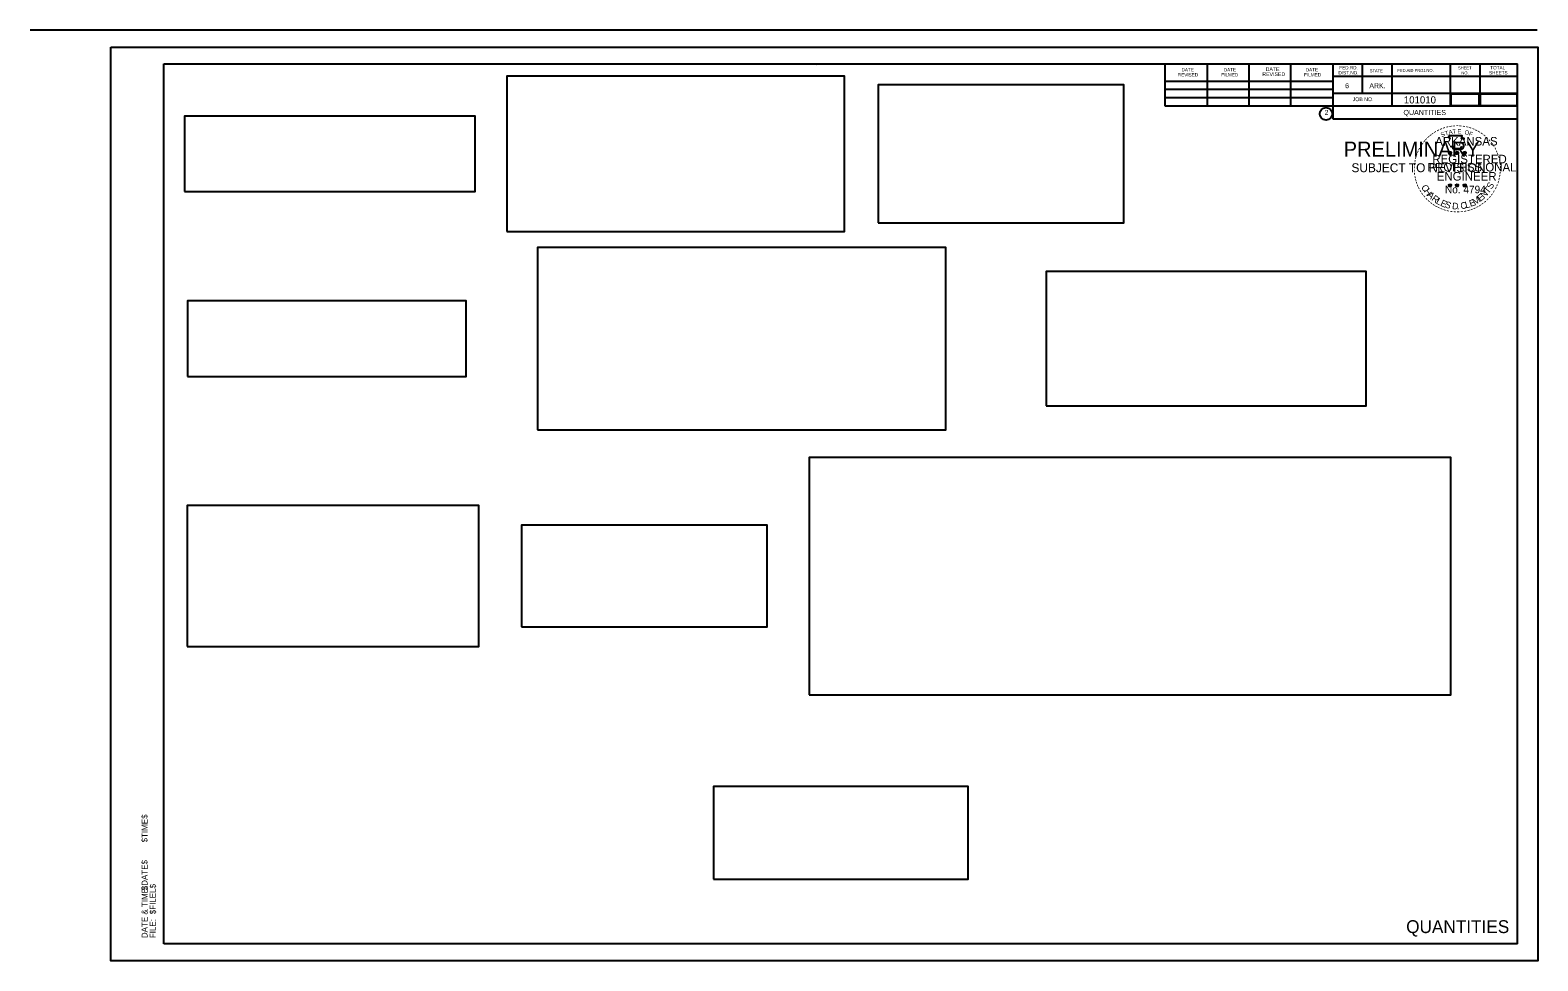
# Model space of a CAD drawing. Extents: x 9844 to 18514, y 8651 to 12569.
# Drawn here: x 11618 to 13378, y 9980 to 11067 of the extents above; entities that cross this region are included whole.
import ezdxf

# ---------------------------------------------------------------- set-up
doc = ezdxf.new("R2010")
doc.units = 0
for name, color, linetype in [('_Drafting 1', 7, 'Continuous'), ('Default', 7, 'Continuous'), ('Quantities', 7, 'Continuous'), ('R_Border Notes', 7, 'Continuous'), ('R_No Plot', 7, 'Continuous'), ('STAMP_PE_CRAFTON-SIGNATURE', 7, 'Continuous'), ('STAMP_PE_SEAL-INFO', 7, 'Continuous'), ('STAMP_PE_TXT', 7, 'Continuous'), ('STAMP_PRELIMINARY', 7, 'Continuous'), ('Total_Pages', 7, 'Continuous')]:
    doc.layers.add(name, color=color, linetype=linetype)

msp = doc.modelspace()

# ---------------------------------------------------------------- linework, layer by layer
at = {"layer": '_Drafting 1'}
for points in [[(11801, 10347), (12141.6, 10347), (12141.6, 10511.6), (11801, 10511.6)], [(12191.5, 10369.9), (12478.5, 10369.9), (12478.5, 10488.7), (12191.5, 10488.7)]]:
    msp.add_lwpolyline(points, close=True, dxfattribs=at)
at = {"layer": 'Quantities'}
for points in [[(12174.5, 10831.6), (12568.8, 10831.6), (12568.8, 11012.9), (12174.5, 11012.9)], [(12608.1, 10841.8), (12895.1, 10841.8), (12895.1, 11002.7), (12608.1, 11002.7)], [(11798.1, 10878.2), (12137.6, 10878.2), (12137.6, 10966.3), (11798.1, 10966.3)], [(12210.4, 10600), (12686.9, 10600), (12686.9, 10813.1), (12210.4, 10813.1)], [(12804.3, 10628), (13178.1, 10628), (13178.1, 10785.1), (12804.3, 10785.1)], [(11801.4, 10662.5), (12126.9, 10662.5), (12126.9, 10750.6), (11801.4, 10750.6)], [(12527.3, 10290.8), (13276.8, 10290.8), (13276.8, 10567.9), (12527.3, 10567.9)], [(12415.6, 10075.4), (12713, 10075.4), (12713, 10183.7), (12415.6, 10183.7)]]:
    msp.add_lwpolyline(points, close=True, dxfattribs=at)
at = {"layer": 'R_No Plot'}
msp.add_lwpolyline([(13276.7, 10978.6), (13310, 10978.6), (13310, 10991.9), (13276.7, 10991.9)], close=True, dxfattribs=at)
at = {"layer": 'STAMP_PE_SEAL-INFO'}
msp.add_lwpolyline([(11711.8, 11046.8), (13378.5, 11046.8), (13378.5, 9980.1), (11711.8, 9980.1)], close=True, dxfattribs=at)
at = {"layer": 'STAMP_PE_TXT'}
for p, q in [((13274.1, 10924), (13275.9, 10923.5)), ((13274.1, 10924), (13275.4, 10923.8)), ((13274.1, 10924), (13275.3, 10923.4)), ((13274.8, 10922), (13275.9, 10923.5)), ((13274.8, 10922), (13275.4, 10923.2)), ((13274.8, 10922), (13275.8, 10923.1)), ((13275.9, 10925.3), (13275.7, 10924.1)), ((13276.9, 10922), (13275.8, 10923.1)), ((13275.9, 10923.5), (13275.9, 10925.3)), ((13275.9, 10925.3), (13276.1, 10924.1)), ((13277.6, 10924), (13275.9, 10923.5)), ((13276.9, 10922), (13275.9, 10923.5)), ((13277.6, 10924), (13276.2, 10923.8)), ((13276.9, 10922), (13276.2, 10923.5)), ((13277.6, 10924), (13276.6, 10923.5)), ((13282.5, 10924), (13284.2, 10923.5)), ((13282.5, 10924), (13283.7, 10923.8)), ((13282.5, 10924), (13283.6, 10923.4)), ((13283.1, 10922), (13284.2, 10923.5)), ((13283.1, 10922), (13283.8, 10923.2)), ((13283.1, 10922), (13284.2, 10923.1)), ((13284.2, 10925.3), (13284, 10924.1)), ((13284.2, 10923.5), (13284.2, 10925.3)), ((13284.2, 10925.3), (13284.5, 10924.1)), ((13285.9, 10924), (13284.2, 10923.5)), ((13285.3, 10922), (13284.2, 10923.5)), ((13285.3, 10922), (13284.2, 10923.1)), ((13285.9, 10924), (13284.5, 10923.8)), ((13285.3, 10922), (13284.6, 10923.5)), ((13285.9, 10924), (13284.9, 10923.5)), ((13291.3, 10924), (13293, 10923.4)), ((13291.3, 10924), (13292.5, 10923.8)), ((13291.3, 10924), (13292.5, 10923.4)), ((13291.9, 10921.9), (13293, 10923.4)), ((13291.9, 10921.9), (13292.6, 10923.2)), ((13291.9, 10921.9), (13293, 10923)), ((13293, 10925.3), (13292.8, 10924)), ((13293, 10923.4), (13293, 10925.3)), ((13293, 10925.3), (13293.3, 10924)), ((13294.8, 10924), (13293, 10923.4)), ((13294.1, 10921.9), (13293, 10923.4)), ((13294.1, 10921.9), (13293, 10923)), ((13294.8, 10924), (13293.3, 10923.7)), ((13294.1, 10921.9), (13293.4, 10923.4)), ((13294.8, 10924), (13293.7, 10923.5)), ((13274.1, 10886.2), (13275.8, 10885.6)), ((13274.1, 10886.2), (13275.4, 10886)), ((13274.1, 10886.2), (13275.3, 10885.6)), ((13274.8, 10884.1), (13275.8, 10885.6)), ((13274.8, 10884.1), (13275.4, 10885.4)), ((13274.8, 10884.1), (13275.8, 10885.2)), ((13275.8, 10887.4), (13275.6, 10886.2)), ((13275.8, 10885.6), (13275.8, 10887.4)), ((13275.8, 10887.4), (13276.1, 10886.2)), ((13277.6, 10886.2), (13275.8, 10885.6)), ((13276.9, 10884.1), (13275.8, 10885.6)), ((13276.9, 10884.1), (13275.8, 10885.2)), ((13277.6, 10886.2), (13276.1, 10885.9)), ((13276.9, 10884.1), (13276.2, 10885.6)), ((13277.6, 10886.2), (13276.6, 10885.7)), ((13282.4, 10886.2), (13284.2, 10885.6)), ((13282.4, 10886.2), (13283.7, 10886)), ((13282.4, 10886.2), (13283.6, 10885.6)), ((13283.1, 10884.1), (13284.2, 10885.6)), ((13283.1, 10884.1), (13283.7, 10885.4)), ((13283.1, 10884.1), (13284.2, 10885.2)), ((13284.2, 10887.4), (13284, 10886.2)), ((13284.2, 10885.6), (13284.2, 10887.4)), ((13284.2, 10887.4), (13284.4, 10886.2)), ((13285.9, 10886.2), (13284.2, 10885.6)), ((13285.2, 10884.1), (13284.2, 10885.6)), ((13285.2, 10884.1), (13284.2, 10885.2)), ((13285.9, 10886.2), (13284.5, 10885.9)), ((13285.2, 10884.1), (13284.6, 10885.6)), ((13285.9, 10886.2), (13284.9, 10885.7)), ((13291.3, 10886.1), (13293, 10885.6)), ((13291.3, 10886.1), (13292.5, 10885.9)), ((13291.3, 10886.1), (13292.5, 10885.5)), ((13291.9, 10884.1), (13293, 10885.6)), ((13291.9, 10884.1), (13292.6, 10885.3)), ((13291.9, 10884.1), (13293, 10885.2)), ((13293, 10887.4), (13292.8, 10886.1)), ((13293, 10885.6), (13293, 10887.4)), ((13293, 10887.4), (13293.3, 10886.1)), ((13294.8, 10886.1), (13293, 10885.6)), ((13294.1, 10884.1), (13293, 10885.6)), ((13294.1, 10884.1), (13293, 10885.2)), ((13294.8, 10886.1), (13293.3, 10885.9)), ((13294.1, 10884.1), (13293.4, 10885.5)), ((13294.8, 10886.1), (13293.7, 10885.6))]:
    msp.add_line(p, q, dxfattribs=at)
for points in [[(13274.3, 10943.4), (13275.7, 10939.3)], [(13291.9, 10938.8), (13292.6, 10940.2), (13289.2, 10940.1), (13289.9, 10943.4), (13274.3, 10943.4)], [(13275.9, 10925.3), (13276.9, 10922), (13274.1, 10924), (13277.6, 10924), (13274.8, 10922), (13275.9, 10925.3)], [(13276.8, 10931.3), (13276.8, 10930.9), (13279.6, 10930.8), (13279.3, 10928.4), (13288.7, 10928.4), (13289.7, 10931.1)], [(13284.2, 10925.3), (13285.3, 10922), (13282.5, 10924), (13285.9, 10924), (13283.1, 10922), (13284.2, 10925.3)], [(13293, 10925.3), (13294.1, 10921.9), (13291.3, 10924), (13294.8, 10924), (13291.9, 10921.9), (13293, 10925.3)], [(13275.8, 10887.4), (13276.9, 10884.1), (13274.1, 10886.2), (13277.6, 10886.2), (13274.8, 10884.1), (13275.8, 10887.4)], [(13284.2, 10887.4), (13285.2, 10884.1), (13282.4, 10886.2), (13285.9, 10886.2), (13283.1, 10884.1), (13284.2, 10887.4)], [(13293, 10887.4), (13294.1, 10884.1), (13291.3, 10886.1), (13294.8, 10886.1), (13291.9, 10884.1), (13293, 10887.4)]]:
    msp.add_lwpolyline(points, dxfattribs=at)
for centre, radius in [((13275.9, 10923.5), 0.861), ((13275.9, 10923.5), 0.723), ((13275.9, 10923.5), 0.579), ((13275.9, 10923.5), 0.495), ((13275.9, 10923.5), 0.374), ((13275.9, 10923.5), 0.248), ((13275.9, 10923.5), 0.148), ((13284.2, 10923.5), 0.861), ((13284.2, 10923.5), 0.723), ((13284.2, 10923.5), 0.579), ((13284.2, 10923.5), 0.495), ((13284.2, 10923.5), 0.374), ((13284.2, 10923.5), 0.248), ((13284.2, 10923.5), 0.148), ((13293, 10923.4), 0.861), ((13293, 10923.4), 0.723), ((13293, 10923.4), 0.579), ((13293, 10923.4), 0.495), ((13293, 10923.4), 0.374), ((13293, 10923.4), 0.248), ((13293, 10923.4), 0.148), ((13275.8, 10885.6), 0.861), ((13275.8, 10885.6), 0.723), ((13275.8, 10885.6), 0.579), ((13275.8, 10885.6), 0.495), ((13275.8, 10885.6), 0.374), ((13275.8, 10885.6), 0.248), ((13275.8, 10885.6), 0.148), ((13284.2, 10885.6), 0.861), ((13284.2, 10885.6), 0.723), ((13284.2, 10885.6), 0.579), ((13284.2, 10885.6), 0.495), ((13284.2, 10885.6), 0.374), ((13284.2, 10885.6), 0.248), ((13284.2, 10885.6), 0.148), ((13293, 10885.6), 0.861), ((13293, 10885.6), 0.723), ((13293, 10885.6), 0.579), ((13293, 10885.6), 0.495), ((13293, 10885.6), 0.374), ((13293, 10885.6), 0.248), ((13293, 10885.6), 0.148)]:
    msp.add_circle(centre, radius, dxfattribs=at)
at = {"layer": 'STAMP_PRELIMINARY'}
for p, q in [((13377.7, 11066.7), (11617.7, 11066.7)), ((11773.8, 11027.3), (13354.7, 11027.3)), ((11773.8, 10000), (11773.8, 11027.3)), ((12536.4, 11026), (12536.4, 11026)), ((12536.4, 11026), (12536.4, 11026)), ((12943.4, 10977.9), (12943.4, 11027.3)), ((12992.7, 10977.9), (12992.7, 11026.3)), ((13041.5, 10977.9), (13041.5, 11026.3)), ((13089.9, 10977.9), (13089.9, 11026.3)), ((13139.2, 11027.3), (13139.2, 10963.3)), ((13173.4, 11027.3), (13173.4, 10992.6)), ((13208.1, 11027.3), (13208.1, 10977.9)), ((13276, 11027.3), (13276, 10977.9)), ((13310.7, 11027.3), (13310.7, 10977.9)), ((13354.7, 10000), (13354.7, 11027.3)), ((12943.4, 11007.2), (13139.2, 11007.2)), ((13354.7, 11012.6), (13139.2, 11012.6)), ((13354.7, 11012.7), (13354.7, 11012.7)), ((12943.4, 10997.9), (13139.2, 10997.9)), ((12943.4, 10988.2), (13139.2, 10988.2)), ((13354.7, 10992.6), (13139.2, 10992.6)), ((13354.7, 10977.9), (12943.4, 10977.9)), ((13139.2, 10963.3), (13354.7, 10963.3)), ((13354.7, 10000), (11773.8, 10000))]:
    msp.add_line(p, q, dxfattribs=at)
msp.add_circle((13131.1, 10969), 7.33, dxfattribs=at)
at = {"layer": 'Total_Pages'}
msp.add_lwpolyline([(13311.2, 10978.6), (13354.2, 10978.6), (13354.2, 10991.9), (13311.2, 10991.9)], close=True, dxfattribs=at)

# ---------------------------------------------------------------- texts
at = {"layer": 'Default'}
for s, height, p in [('$TIME$', 6.98, (11754.8, 10118.4)), ('$DATE$', 6.98, (11754.8, 10062.5)), ('DATE & TIME:', 6.984, (11754.8, 10006.6)), ('$FILEL$', 6.98, (11764.4, 10034.5)), ('FILE: ', 6.98, (11764.4, 10006.6))]:
    msp.add_text(s, height=height, rotation=90, dxfattribs=at).set_placement(p)
at = {"layer": 'R_Border Notes'}
for s, height, p in [('101010', 8.4, (13222, 10981.1)), ('QUANTITIES', 6, (13221.5, 10967.6))]:
    msp.add_text(s, height=height, dxfattribs=at).set_placement(p)
at = {"layer": 'STAMP_PE_CRAFTON-SIGNATURE'}
for s, height, p in [('PRELIMINARY', 17.5, (13151.7, 10919)), ('SUBJECT TO REVISION', 10.376, (13160.8, 10900.9))]:
    msp.add_text(s, height=height, dxfattribs=at).set_placement(p)
at = {"layer": 'STAMP_PE_TXT'}
for s, height, rotation, p in [('-', 8, 24.3072, (13264.9, 10947.7)), ('-', 8, 19.1761, (13268.1, 10949.1)), ('-', 8, 13.6302, (13271.8, 10950.3)), ('-', 8, 10.2193, (13275.2, 10951.1)), ('-', 8, 5.8968, (13278.8, 10951.6)), ('-', 8, 0.1862, (13282.7, 10952)), ('-', 8, 357.743, (13286.3, 10951.9)), ('-', 8, 352.1617, (13290, 10951.6)), ('-', 8, 347.2049, (13293.6, 10951.1)), ('-', 8, 342.3362, (13296.8, 10950.3)), ('-', 8, 337.8551, (13300.5, 10949.2)), ('-', 8, 54.2325, (13245, 10930.7)), ('-', 8, 50.6142, (13247, 10933.5)), ('-', 8, 48.4231, (13249.1, 10935.9)), ('-', 8, 42.9622, (13251.3, 10938.3)), ('-', 8, 38.9507, (13253.5, 10940.4)), ('-', 8, 36.2317, (13255.8, 10942.3)), ('-', 8, 34.0636, (13258.7, 10944.3)), ('-', 8, 28.7918, (13261.7, 10946.1)), ('S', 5, 21.594, (13266.1, 10941.8)), ('T', 5, 16.4036, (13270.7, 10943.5)), ('A', 5, 11.2132, (13274.8, 10944.7)), ('T', 5, 6.0228, (13279, 10945.6)), ('E', 5, 0.8323, (13284.6, 10946.1)), ('O', 5, 350.4515, (13292.6, 10945.1)), ('F', 5, 340.0707, (13297.4, 10943.9)), ('-', 8, 334.1211, (13303.6, 10947.8)), ('-', 8, 329.6409, (13306.5, 10946.4)), ('-', 8, 325.8627, (13309.7, 10944.6)), ('-', 8, 320.5297, (13312.8, 10942.5)), ('-', 8, 315.5786, (13315.8, 10940)), ('-', 8, 309.8797, (13318.6, 10937.3)), ('-', 8, 306.6522, (13321.3, 10934.3)), ('-', 8, 75.461, (13238.4, 10915.2)), ('-', 8, 72.3945, (13239.4, 10918.8)), ('-', 8, 67.7743, (13240.5, 10921.9)), ('-', 8, 62.8713, (13241.8, 10925)), ('-', 8, 58.0706, (13243.4, 10928)), ('-', 7, 303.6753, (13323.7, 10931.4)), ('-', 8, 299.6684, (13325.3, 10928.4)), ('-', 8, 294.6628, (13326.9, 10925.3)), ('-', 8, 290.5728, (13328.2, 10922.5)), ('-', 8, 285.1233, (13329.4, 10919.6)), ('-', 8, 89.0622, (13237.3, 10904.7)), ('-', 8, 94.1959, (13237.4, 10901.1)), ('-', 8, 98.9479, (13237.8, 10897.7)), ('-', 8, 85.1863, (13237.4, 10908.2)), ('-', 8, 81.2013, (13237.8, 10911.6)), ('-', 8, 280.5493, (13330.4, 10915.9)), ('-', 8, 276.5962, (13331.2, 10912)), ('-', 8, 263.5172, (13331.5, 10901.9)), ('-', 8, 274.3301, (13331.5, 10908.4)), ('-', 8, 269.9407, (13331.6, 10905.2)), ('-', 8, 101.7149, (13238.5, 10894.1)), ('-', 8, 105.4578, (13239.3, 10891.1)), ('-', 8, 109.0874, (13240.3, 10887.9)), ('-', 8, 114.0643, (13241.6, 10884.9)), ('-', 8, 115.7289, (13243.1, 10881.9)), ('C', 7.7, 296.9133, (13242, 10883.9)), ('H', 7.7, 303.2799, (13244.9, 10878.7)), ('T', 7.7, 51.5114, (13320.7, 10875.1)), ('S', 7.7, 57.878, (13324.3, 10880.3)), ('-', 8, 244.6197, (13327.3, 10885.1)), ('-', 8, 247.8887, (13328.6, 10888.3)), ('-', 8, 255.7626, (13329.7, 10891.8)), ('-', 8, 255.7626, (13330.6, 10895.3)), ('-', 8, 260.9953, (13331.2, 10898.6)), ('-', 8, 120.4471, (13244.9, 10878.9)), ('-', 8, 125.8934, (13246.9, 10876.1)), ('-', 8, 130.7181, (13249.3, 10873.4)), ('-', 8, 134.2238, (13251.8, 10870.6)), ('A', 7.7, 316.013, (13248.6, 10873.6)), ('-', 8, 138.9338, (13254.5, 10868.3)), ('-', 8, 144.6463, (13257.2, 10866.3)), ('R', 7.7, 322.3796, (13253.7, 10868.7)), ('L', 7.7, 328.7461, (13258.8, 10864.9)), ('E', 7.7, 335.1127, (13263.9, 10862.1)), ('S', 7.7, 341.4792, (13269.2, 10860)), ('D', 7.7, 354.2124, (13278, 10857.9)), ('C', 7.7, 6.9455, (13288.5, 10857.7)), ('L', 7.7, 13.3121, (13294.4, 10858.7)), ('E', 7.7, 19.6786, (13299.9, 10860.3)), ('M', 7.7, 32.4117, (13305, 10862.1)), ('E', 7.7, 38.7783, (13311.4, 10866.2)), ('N', 7.7, 45.1449, (13315.9, 10869.9)), ('-', 8, 215.7363, (13313.4, 10867.6)), ('-', 8, 221.0851, (13316.2, 10869.9)), ('-', 8, 225.7653, (13318.8, 10872.5)), ('-', 8, 231.2538, (13321.2, 10875.3)), ('-', 8, 233.8452, (13323.3, 10878.1)), ('-', 8, 239.0712, (13325.3, 10881.4)), ('-', 8, 148.0898, (13260, 10864.4)), ('-', 8, 151.5704, (13262.9, 10862.8)), ('-', 8, 154.6002, (13265.6, 10861.6)), ('-', 8, 158.5612, (13268.7, 10860.3)), ('-', 8, 162.7983, (13272.1, 10859.2)), ('-', 8, 167.5555, (13275.7, 10858.4)), ('-', 8, 173.1155, (13279.5, 10857.9)), ('-', 8, 176.5183, (13283.3, 10857.6)), ('-', 8, 181.5918, (13287, 10857.7)), ('.', 7.7, 0.5789, (13283.9, 10857.5)), ('-', 8, 185.8167, (13291, 10858.1)), ('-', 8, 191.2858, (13294.7, 10858.7)), ('-', 8, 195.4743, (13298.4, 10859.7)), ('-', 8, 200.7184, (13301.8, 10860.9)), ('-', 8, 204.2516, (13304.9, 10862.3)), ('-', 8, 207.3568, (13308, 10863.9)), ('-', 8, 212.2491, (13310.8, 10865.6))]:
    msp.add_text(s, height=height, rotation=rotation, dxfattribs=at).set_placement(p)
for s, height, p in [('ARKANSAS', 10, (13258.6, 10932)), ('REGISTERED', 10, (13255.2, 10911.2)), ('PROFESSIONAL', 10, (13249.5, 10901.7)), ('ENGINEER', 10, (13260.4, 10891.1)), ('No. 4794', 8.78, (13270, 10876.3))]:
    msp.add_text(s, height=height, dxfattribs=at).set_placement(p)
at = {"layer": 'STAMP_PRELIMINARY'}
for s, height, p in [('DATE', 3.91, (12962.4, 11018.5)), ('DATE', 3.91, (13011.7, 11018.5)), ('DATE', 4.4, (13060.6, 11019)), ('DATE', 3.91, (13107.5, 11018.5)), ('FED.RD.', 3.91, (13146.6, 11020.9)), ('SHEET', 3.42, (13285.3, 11020.9)), ('TOTAL', 3.91, (13322.9, 11020.9)), ('REVISED', 3.91, (12958, 11012.6)), ('FILMED', 3.91, (13008.8, 11012.6)), ('REVISED', 4.4, (13056.7, 11013.1)), ('FILMED', 3.91, (13105.5, 11012.6)), ('DIST.NO.', 3.91, (13145.6, 11015)), ('6', 5.86, (13153.4, 10998.9)), ('STATE', 3.42, (13182.2, 11017.5)), ('FED.AID PROJ.NO.', 3.42, (13214.5, 11018)), ('NO.', 3.42, (13289.2, 11015)), ('SHEETS', 3.91, (13321.5, 11015)), ('JOB NO.', 4.4, (13162.2, 10983.8)), ('ARK.', 5.86, (13181.7, 10998.9)), ('2', 5.86, (13129.5, 10967.7)), ('QUANTITIES', 15, (13224.7, 10012.5))]:
    msp.add_text(s, height=height, dxfattribs=at).set_placement(p)

doc.saveas('drawing.dxf')
